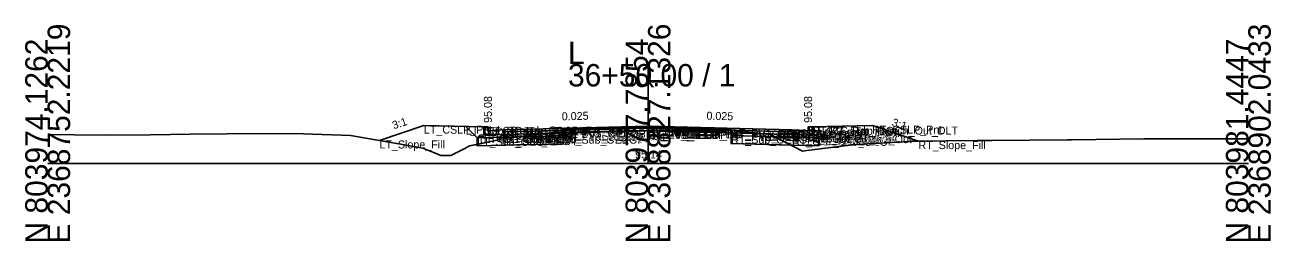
# Model space of a CAD drawing. Extents: x -26 to 8153, y -10 to 9520.
# Drawn here: x 2997.2 to 3152.8, y 2490.3 to 2517.3 of the extents above; entities that cross this region are included whole.
import ezdxf

# ---------------------------------------------------------------- set-up
doc = ezdxf.new("R2010")
doc.units = 0
for name, color, linetype in [('Exist CMT Pavement', 7, 'Continuous'), ('Exist Cross Section Cell', 7, 'Continuous'), ('Exist XS Center Line Elevation Label', 7, 'Continuous'), ('Exist XS Ground Line', 7, 'Continuous'), ('Prop CMT Conc Surface', 7, 'Continuous'), ('Prop CMT Concrete Structures', 7, 'Continuous'), ('Prop CMT Pvmt Course 1', 7, 'Continuous'), ('Prop CMT Pvmt Course 1 CG', 7, 'Continuous'), ('Prop CMT Pvmt Course 1 Wedge', 7, 'Continuous'), ('Prop CMT Pvmt Course 2', 7, 'Continuous'), ('Prop CMT Pvmt Course 2 Wedge', 7, 'Continuous'), ('Prop CMT Pvmt Course 3', 7, 'Continuous'), ('Prop CMT Pvmt Course 3 Wedge', 7, 'Continuous'), ('Prop CMT Pvmt Surface', 7, 'Continuous'), ('Prop CMT Pvmt Wedge Surface 1', 7, 'Continuous'), ('Prop CMT Pvmt Wedge Surface 2', 7, 'Continuous'), ('Prop CMT Pvmt Wedge Surface 3', 7, 'Continuous'), ('Prop CMT Shallow Undercut', 7, 'Continuous'), ('Prop CMT Shallow Undercut Boundary', 7, 'Continuous'), ('Prop CMT Slope Grass', 7, 'Continuous'), ('Prop CMT Subgrade Earthwork', 7, 'Continuous'), ('Prop XS Earthwork Shape', 7, 'Continuous'), ('Prop XS Hydro Elevations', 7, 'Continuous'), ('Prop XS SE Text', 7, 'Continuous'), ('Prop XS Side Slope Text', 7, 'Continuous'), ('Prop XS Subgrade Earthwork', 7, 'Continuous'), ('Scratch_Level_2', 7, 'Continuous'), ('Scratch_Level_6', 7, 'Continuous')]:
    doc.layers.add(name, color=color, linetype=linetype)

msp = doc.modelspace()

# ---------------------------------------------------------------- linework, layer by layer
at = {"layer": 'Exist CMT Pavement'}
for p, q in [((3064.38, 2503.92), (3066.47, 2503.97)), ((3066.47, 2503.97), (3074.76, 2504.14)), ((3074.76, 2504.14), (3083.26, 2504.12)), ((3083.26, 2504.12), (3085.37, 2504.12))]:
    msp.add_line(p, q, dxfattribs=at)
at = {"layer": 'Exist Cross Section Cell'}
for p, q in [((3075, 2500), (3075, 2512.43)), ((3000, 2500), (3075, 2500)), ((3075, 2500), (3150, 2500))]:
    msp.add_line(p, q, dxfattribs=at)
at = {"layer": 'Exist XS Ground Line'}
for p, q in [((3000, 2503.63), (3003.31, 2503.6)), ((3003.31, 2503.6), (3007.81, 2503.56)), ((3007.81, 2503.56), (3012.86, 2503.6)), ((3012.86, 2503.6), (3017.82, 2503.65)), ((3017.82, 2503.65), (3022.4, 2503.7)), ((3022.4, 2503.7), (3027.83, 2503.76)), ((3027.83, 2503.76), (3031.95, 2503.7)), ((3031.95, 2503.7), (3037.85, 2503.5)), ((3037.85, 2503.5), (3044.09, 2502.42)), ((3058.54, 2503.28), (3062.19, 2503.79)), ((3062.19, 2503.79), (3063.62, 2503.87)), ((3063.62, 2503.87), (3064.38, 2503.92)), ((3064.38, 2503.92), (3066.47, 2503.97)), ((3066.47, 2503.97), (3074.76, 2504.14)), ((3074.76, 2504.14), (3083.26, 2504.12)), ((3083.26, 2504.12), (3085.37, 2504.12)), ((3085.37, 2504.12), (3087.99, 2503.86)), ((3087.99, 2503.86), (3090.3, 2503.61)), ((3090.3, 2503.61), (3093.41, 2502.02)), ((3044.09, 2502.42), (3046.88, 2501.93)), ((3046.88, 2501.93), (3048.13, 2501.43)), ((3050.35, 2501.01), (3052.1, 2501.88)), ((3052.1, 2501.88), (3052.71, 2502.2)), ((3052.71, 2502.2), (3055.01, 2502.65)), ((3055.01, 2502.65), (3056.87, 2503.07)), ((3056.87, 2503.07), (3058.54, 2503.28)), ((3093.41, 2502.02), (3094.3, 2501.56)), ((3094.86, 2501.61), (3098.83, 2502.14)), ((3098.83, 2502.14), (3100.99, 2502.37)), ((3100.99, 2502.37), (3106.87, 2502.72)), ((3106.87, 2502.72), (3107.93, 2502.79)), ((3107.93, 2502.79), (3108.32, 2502.8)), ((3108.32, 2502.8), (3116.17, 2502.86)), ((3116.17, 2502.86), (3117.95, 2502.88)), ((3117.95, 2502.88), (3127.41, 2502.98)), ((3127.41, 2502.98), (3127.96, 2502.98)), ((3127.96, 2502.98), (3136.95, 2503.1)), ((3136.95, 2503.1), (3137.97, 2503.1)), ((3137.97, 2503.1), (3146.5, 2503.07)), ((3146.5, 2503.07), (3147.98, 2503.09)), ((3147.98, 2503.09), (3150, 2503.08)), ((3048.13, 2501.43), (3049.11, 2501)), ((3049.11, 2501), (3049.68, 2501.01)), ((3049.68, 2501.01), (3050.35, 2501.01)), ((3094.3, 2501.56), (3094.86, 2501.61))]:
    msp.add_line(p, q, dxfattribs=at)
at = {"layer": 'Prop CMT Conc Surface'}
for points in [[(3055, 2504.08), (3055, 2504.58), (3054.5, 2504.58)], [(3057, 2504.21), (3055, 2504.08)], [(3093, 2504.21), (3095, 2504.08)], [(3095, 2504.08), (3095, 2504.58), (3095.5, 2504.58)]]:
    msp.add_lwpolyline(points, dxfattribs=at)
at = {"layer": 'Prop CMT Concrete Structures'}
for points in [[(3057, 2504.21), (3055, 2504.08), (3055, 2504.58), (3054.5, 2504.58)], [(3054.5, 2504.58), (3054.5, 2503.56), (3057, 2503.63)], [(3057, 2503.63), (3057, 2504.21)], [(3093, 2504.21), (3095, 2504.08), (3095, 2504.58), (3095.5, 2504.58)], [(3095.5, 2504.58), (3095.5, 2503.56), (3093, 2503.63)], [(3093, 2503.63), (3093, 2504.21)]]:
    msp.add_lwpolyline(points, dxfattribs=at)
at = {"layer": 'Prop CMT Pvmt Course 1'}
for points in [[(3075, 2504.66), (3057, 2504.21)], [(3057, 2504.21), (3057, 2503.96)], [(3057, 2503.96), (3064.38, 2504.14)], [(3064.38, 2504.27), (3075, 2504.53)], [(3064.38, 2504.14), (3064.38, 2504.27)], [(3075, 2504.41), (3075, 2504.66)], [(3075, 2504.66), (3093, 2504.21)], [(3075, 2504.41), (3075, 2504.66)], [(3075, 2504.53), (3075, 2504.41), (3075, 2504.41)], [(3085.37, 2504.27), (3075, 2504.53)], [(3075, 2504.53), (3075, 2504.41), (3075, 2504.41)], [(3085.37, 2504.15), (3085.37, 2504.27)], [(3093, 2503.96), (3085.37, 2504.15)], [(3093, 2504.21), (3093, 2503.96)]]:
    msp.add_lwpolyline(points, dxfattribs=at)
at = {"layer": 'Prop CMT Pvmt Course 1 CG'}
for points in [[(3057, 2503.63), (3054, 2503.55), (3053.66, 2503.21)], [(3057, 2503.3), (3057, 2503.63)], [(3093, 2503.63), (3096, 2503.55), (3096.34, 2503.21)], [(3093, 2503.3), (3093, 2503.63)], [(3053.66, 2503.21), (3057, 2503.3)], [(3096.34, 2503.21), (3093, 2503.3)]]:
    msp.add_lwpolyline(points, dxfattribs=at)
at = {"layer": 'Prop CMT Pvmt Course 1 Wedge'}
for points in [[(3075, 2504.53), (3064.38, 2504.27)], [(3075, 2504.53), (3085.37, 2504.27)]]:
    msp.add_lwpolyline(points, dxfattribs=at)
at = {"layer": 'Prop CMT Pvmt Course 2'}
for points in [[(3064.38, 2504.14), (3057, 2503.96)], [(3057, 2503.96), (3057, 2503.63)], [(3057, 2503.63), (3064.38, 2503.81)], [(3064.38, 2503.81), (3064.38, 2504.14)], [(3085.37, 2503.82), (3085.37, 2504.15)], [(3085.37, 2504.15), (3093, 2503.96)], [(3093, 2503.63), (3085.37, 2503.82)], [(3093, 2503.96), (3093, 2503.63)]]:
    msp.add_lwpolyline(points, dxfattribs=at)
at = {"layer": 'Prop CMT Pvmt Course 2 Wedge'}
for points in [[(3075, 2504.41), (3064.38, 2504.14)], [(3075, 2504.41), (3085.37, 2504.15)]]:
    msp.add_lwpolyline(points, dxfattribs=at)
at = {"layer": 'Prop CMT Pvmt Course 3'}
for points in [[(3064.38, 2503.81), (3057, 2503.63)], [(3057, 2503.63), (3057, 2503.3)], [(3057, 2503.3), (3064.38, 2503.48)], [(3064.38, 2503.48), (3064.38, 2503.81)], [(3085.37, 2503.82), (3093, 2503.63)], [(3085.37, 2503.49), (3085.37, 2503.82)], [(3093, 2503.3), (3085.37, 2503.49)], [(3093, 2503.63), (3093, 2503.3)]]:
    msp.add_lwpolyline(points, dxfattribs=at)
at = {"layer": 'Prop CMT Pvmt Course 3 Wedge'}
for points in [[(3075, 2504.08), (3064.38, 2503.81)], [(3075, 2504.08), (3085.37, 2503.82)]]:
    msp.add_lwpolyline(points, dxfattribs=at)
at = {"layer": 'Prop CMT Pvmt Surface'}
for points in [[(3075, 2504.66), (3057, 2504.21)], [(3075, 2504.66), (3093, 2504.21)]]:
    msp.add_lwpolyline(points, dxfattribs=at)
at = {"layer": 'Prop CMT Pvmt Wedge Surface 1'}
for points in [[(3057, 2503.96), (3057, 2504.21)], [(3064.38, 2504.14), (3057, 2503.96)], [(3075, 2504.53), (3064.38, 2504.27)], [(3064.38, 2504.27), (3064.38, 2504.14)], [(3075, 2504.53), (3085.37, 2504.27)], [(3085.37, 2504.27), (3085.37, 2504.15)], [(3085.37, 2504.15), (3093, 2503.96)], [(3093, 2503.96), (3093, 2504.21)]]:
    msp.add_lwpolyline(points, dxfattribs=at)
at = {"layer": 'Prop CMT Pvmt Wedge Surface 2'}
for points in [[(3075, 2504.41), (3057, 2503.96)], [(3057, 2503.96), (3057, 2504.21)], [(3075, 2504.41), (3093, 2503.96)], [(3093, 2503.96), (3093, 2504.21)]]:
    msp.add_lwpolyline(points, dxfattribs=at)
at = {"layer": 'Prop CMT Pvmt Wedge Surface 3'}
for points in [[(3057, 2503.63), (3057, 2504.21)], [(3075, 2504.08), (3057, 2503.63)], [(3075, 2504.08), (3093, 2503.63)], [(3093, 2503.63), (3093, 2504.21)]]:
    msp.add_lwpolyline(points, dxfattribs=at)
at = {"layer": 'Prop CMT Shallow Undercut'}
for points in [[(3056.87, 2503.07), (3058.54, 2503.28), (3059, 2503.35), (3064.38, 2503.48), (3064.38, 2502.48), (3053.66, 2502.21), (3053.66, 2502.39), (3055.01, 2502.65)], [(3090.82, 2503.35), (3092.87, 2502.3), (3085.37, 2502.49), (3085.37, 2503.49)]]:
    msp.add_lwpolyline(points, close=True, dxfattribs=at)
at = {"layer": 'Prop CMT Shallow Undercut Boundary'}
for p, q in [((3064.38, 2503.48), (3064.38, 2502.48)), ((3085.37, 2503.49), (3085.37, 2502.49)), ((3053.66, 2503.21), (3053.66, 2502.21)), ((3053.66, 2502.21), (3064.38, 2502.48)), ((3096.34, 2502.21), (3085.37, 2502.49)), ((3096.34, 2503.21), (3096.34, 2502.21))]:
    msp.add_line(p, q, dxfattribs=at)
at = {"layer": 'Prop CMT Slope Grass'}
for points in [[(3054.5, 2504.58), (3047, 2504.73), (3041.45, 2502.88)], [(3095.5, 2504.58), (3103, 2504.73), (3108.79, 2502.8)]]:
    msp.add_lwpolyline(points, dxfattribs=at)
at = {"layer": 'Prop CMT Subgrade Earthwork'}
for points in [[(3057, 2503.3), (3053.66, 2503.21), (3052.25, 2504.62)], [(3064.38, 2503.48), (3057, 2503.3)], [(3064.38, 2503.48), (3064.4, 2503.92)], [(3085.37, 2503.49), (3085.36, 2504.12)], [(3085.37, 2503.49), (3093, 2503.3)], [(3093, 2503.3), (3096.34, 2503.21), (3097.75, 2504.62)]]:
    msp.add_lwpolyline(points, dxfattribs=at)
at = {"layer": 'Prop XS Earthwork Shape'}
for points in [[(3052.1, 2501.88), (3052.71, 2502.2), (3053.66, 2502.39), (3053.66, 2503.21), (3052.25, 2504.62), (3047, 2504.73), (3041.45, 2502.88), (3044.09, 2502.42), (3046.88, 2501.93), (3048.13, 2501.43), (3049.11, 2501), (3049.68, 2501.01), (3050.35, 2501.01)], [(3053.66, 2502.39), (3055.01, 2502.65), (3056.87, 2503.07), (3058.54, 2503.28), (3059, 2503.35), (3064.38, 2503.48), (3064.38, 2502.48), (3053.66, 2502.21)], [(3064.38, 2503.48), (3064.4, 2503.92), (3064.38, 2503.92), (3063.62, 2503.87), (3062.19, 2503.79), (3059, 2503.35)], [(3085.37, 2503.49), (3090.82, 2503.35), (3090.3, 2503.61), (3087.99, 2503.86), (3085.37, 2504.12), (3085.36, 2504.12)], [(3092.87, 2502.3), (3085.37, 2502.49), (3085.37, 2503.49), (3090.82, 2503.35)], [(3092.87, 2502.3), (3093.41, 2502.02), (3094.3, 2501.56), (3094.86, 2501.61), (3098.83, 2502.14), (3100.99, 2502.37), (3106.87, 2502.72), (3107.93, 2502.79), (3108.32, 2502.8), (3108.79, 2502.8), (3103, 2504.73), (3097.75, 2504.62), (3096.34, 2503.21), (3096.34, 2502.21)], [(3053.66, 2502.39), (3055.01, 2502.65), (3056.87, 2503.07), (3058.54, 2503.28), (3059, 2503.35), (3057, 2503.3), (3053.66, 2503.21)], [(3093, 2503.3), (3096.34, 2503.21), (3096.34, 2502.21), (3092.87, 2502.3), (3090.82, 2503.35)]]:
    msp.add_lwpolyline(points, close=True, dxfattribs=at)
at = {"layer": 'Prop XS Subgrade Earthwork'}
for p, q in [((3053.66, 2503.21), (3064.38, 2503.48)), ((3085.37, 2503.49), (3096.34, 2503.21))]:
    msp.add_line(p, q, dxfattribs=at)
at = {"layer": 'Scratch_Level_6'}
for points in [[(3056.87, 2503.07), (3058.54, 2503.28), (3059, 2503.35), (3064.38, 2503.48), (3064.38, 2502.48), (3053.66, 2502.21), (3053.66, 2502.39), (3055.01, 2502.65)], [(3090.82, 2503.35), (3092.87, 2502.3), (3085.37, 2502.49), (3085.37, 2503.49)]]:
    msp.add_lwpolyline(points, close=True, dxfattribs=at)

# ---------------------------------------------------------------- texts
at = {"layer": 'Exist Cross Section Cell'}
for s, p in [('E 2368752.2219', (3002.8, 2490)), ('E 2368827.1326', (3077.8, 2490)), ('E 2368902.0433', (3152.8, 2490)), ('N 803974.1262', (3000, 2490)), ('N 803977.7854', (3075, 2490)), ('N 803981.4447', (3150, 2490))]:
    msp.add_text(s, height=2.8, rotation=90, dxfattribs=at).set_placement(p)
for s, p in [('L', (3065, 2512.43)), ('36+50.00 / 1', (3065, 2509.63))]:
    msp.add_text(s, height=2.8, dxfattribs=at).set_placement(p)
at = {"layer": 'Exist XS Center Line Elevation Label'}
msp.add_text('95.14', height=1, dxfattribs=at).set_placement((3073.38, 2500.64))
at = {"layer": 'Prop XS Hydro Elevations'}
for p in [(3055.5, 2505.08), (3095.5, 2505.08)]:
    msp.add_text('95.08', height=1, rotation=90, dxfattribs=at).set_placement(p)
at = {"layer": 'Prop XS SE Text'}
for rotation, p in [(358.5679, (3082.29, 2505.48)), (1.4321, (3064.24, 2505.39))]:
    msp.add_text('0.025', height=1, rotation=rotation, dxfattribs=at).set_placement(p)
at = {"layer": 'Prop XS Side Slope Text'}
for rotation, p in [(18.4349, (3043.24, 2504.26)), (341.5651, (3105.38, 2504.73))]:
    msp.add_text('3:1', height=1, rotation=rotation, dxfattribs=at).set_placement(p)
at = {"layer": 'Scratch_Level_2'}
for s, p in [('LT_CSLP_Pnt', (3047, 2503.73)), ('LT_Sub_Trench_Out_DLT', (3052.25, 2503.62)), ('LT_CG1_Shelf_Out', (3054, 2502.55)), ('LT_CG_Top_BOC', (3054.5, 2503.58)), ('LT_CG_Bot_BOC', (3054.5, 2502.56)), ('LT_CG_Top_Face', (3055, 2503.58)), ('LT_CG_Top_Gut', (3055, 2503.08)), ('LT_PV1_OEOT', (3057, 2503.21)), ('LT_PV2_OEOT', (3057, 2502.96)), ('LT_PV3_OEOT', (3057, 2502.63)), ('LT_CG_Bot_IE', (3057, 2502.63)), ('LT_PV1_OEEOP', (3064.38, 2503.27)), ('LT_PV2_OEEOP', (3064.38, 2503.14)), ('LT_PV_OEEOP_EG', (3064.38, 2502.92)), ('LT_PV3_OEEOP', (3064.38, 2502.81)), ('LT_Sub_OEEOP', (3064.38, 2502.48)), ('LT_PV_Sub_Tie_Out', (3064.4, 2502.92)), ('PV1_PGL', (3075, 2503.66)), ('RT_PV1_IEEOP', (3075, 2503.53)), ('LT_PV1_IEEOP', (3075, 2503.53)), ('RT_PV2_IEEOP', (3075, 2503.41)), ('LT_PV2_IEEOP', (3075, 2503.41)), ('PV2_PGL', (3075, 2503.41)), ('RT_PV_IEEOP_EG', (3075, 2503.14)), ('LT_PV_IEEOP_EG', (3075, 2503.14)), ('RT_PV3_IEEOP', (3075, 2503.08)), ('LT_PV3_IEEOP', (3075, 2503.08)), ('RT_PV_Sub_Tie_Out', (3085.36, 2503.12)), ('RT_PV1_OEEOP', (3085.37, 2503.27)), ('RT_PV2_OEEOP', (3085.37, 2503.15)), ('RT_PV_OEEOP_EG', (3085.37, 2503.12)), ('RT_PV3_OEEOP', (3085.37, 2502.82)), ('RT_Sub_OEEOP', (3085.37, 2502.49)), ('RT_PV1_OEOT', (3093, 2503.21)), ('RT_PV2_OEOT', (3093, 2502.96)), ('RT_PV3_OEOT', (3093, 2502.63)), ('RT_CG_Bot_IE', (3093, 2502.63)), ('RT_CG_Top_Face', (3095, 2503.58)), ('RT_CG_Top_Gut', (3095, 2503.08)), ('RT_CG_Top_BOC', (3095.5, 2503.58)), ('RT_CG_Bot_BOC', (3095.5, 2502.56)), ('RT_CG1_Shelf_Out', (3096, 2502.55)), ('RT_Sub_Trench_Out_DLT', (3097.75, 2503.62)), ('RT_CSLP_Pnt', (3103, 2503.73)), ('LT_Slope_Fill', (3041.45, 2501.88)), ('LT_Sub_OEOP', (3053.66, 2502.21)), ('LT_Sub_OEOT', (3057, 2502.3)), ('RT_Sub_OEOT', (3093, 2502.3)), ('RT_Sub_OEOP', (3096.34, 2502.21)), ('RT_Slope_Fill', (3108.79, 2501.8))]:
    msp.add_text(s, height=1, dxfattribs=at).set_placement(p)

doc.saveas('drawing.dxf')
